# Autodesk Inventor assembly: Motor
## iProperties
Created: 2008-07
Part Number: Motor
Document SubType Name: Assembly
Designer: tangg
Mass: 130.161 g
Surface Area: 104.869 cm^2
Volume: 19.3028 cm^3
Density: 6.7431 g/cm^3
Author: tangg
